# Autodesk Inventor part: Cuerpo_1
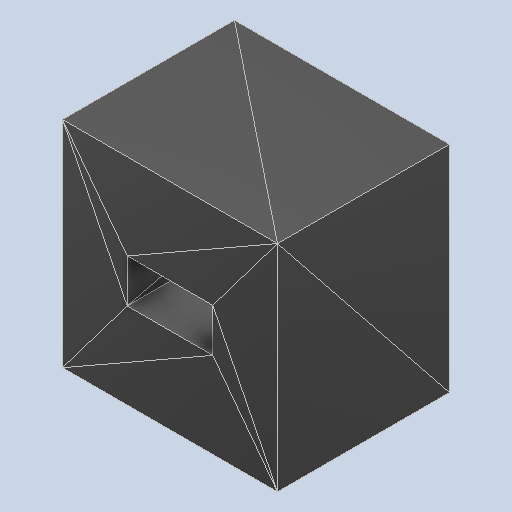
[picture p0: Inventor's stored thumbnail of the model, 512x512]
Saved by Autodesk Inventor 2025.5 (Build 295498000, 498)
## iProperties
Created: 2026-10
Part Number: Cuerpo_1
Material: Genérico
Document SubType Name: Modeling
Designer: Luis M
Density: 1 g/cm^3
Appearance: Valor por defecto
Author: Luis M
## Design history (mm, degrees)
feature "Base1"
node "Sólido1"
